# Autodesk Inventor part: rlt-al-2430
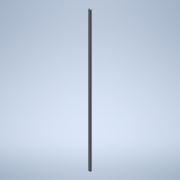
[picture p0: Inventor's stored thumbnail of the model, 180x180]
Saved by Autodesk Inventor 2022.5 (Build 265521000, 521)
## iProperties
Created: 2016-12
Part Number: rlt-al-2430
Material: 一般
Document SubType Name: Modeling
Designer: imaocorp
Density: 1 g/cm^3
Appearance: 既定
Author: imaocorp
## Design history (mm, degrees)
node "rlt-al-2430.x_t1"
node "rlt-al-2430"
node "Base1"
